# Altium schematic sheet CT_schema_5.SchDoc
size 405 x 220 mm
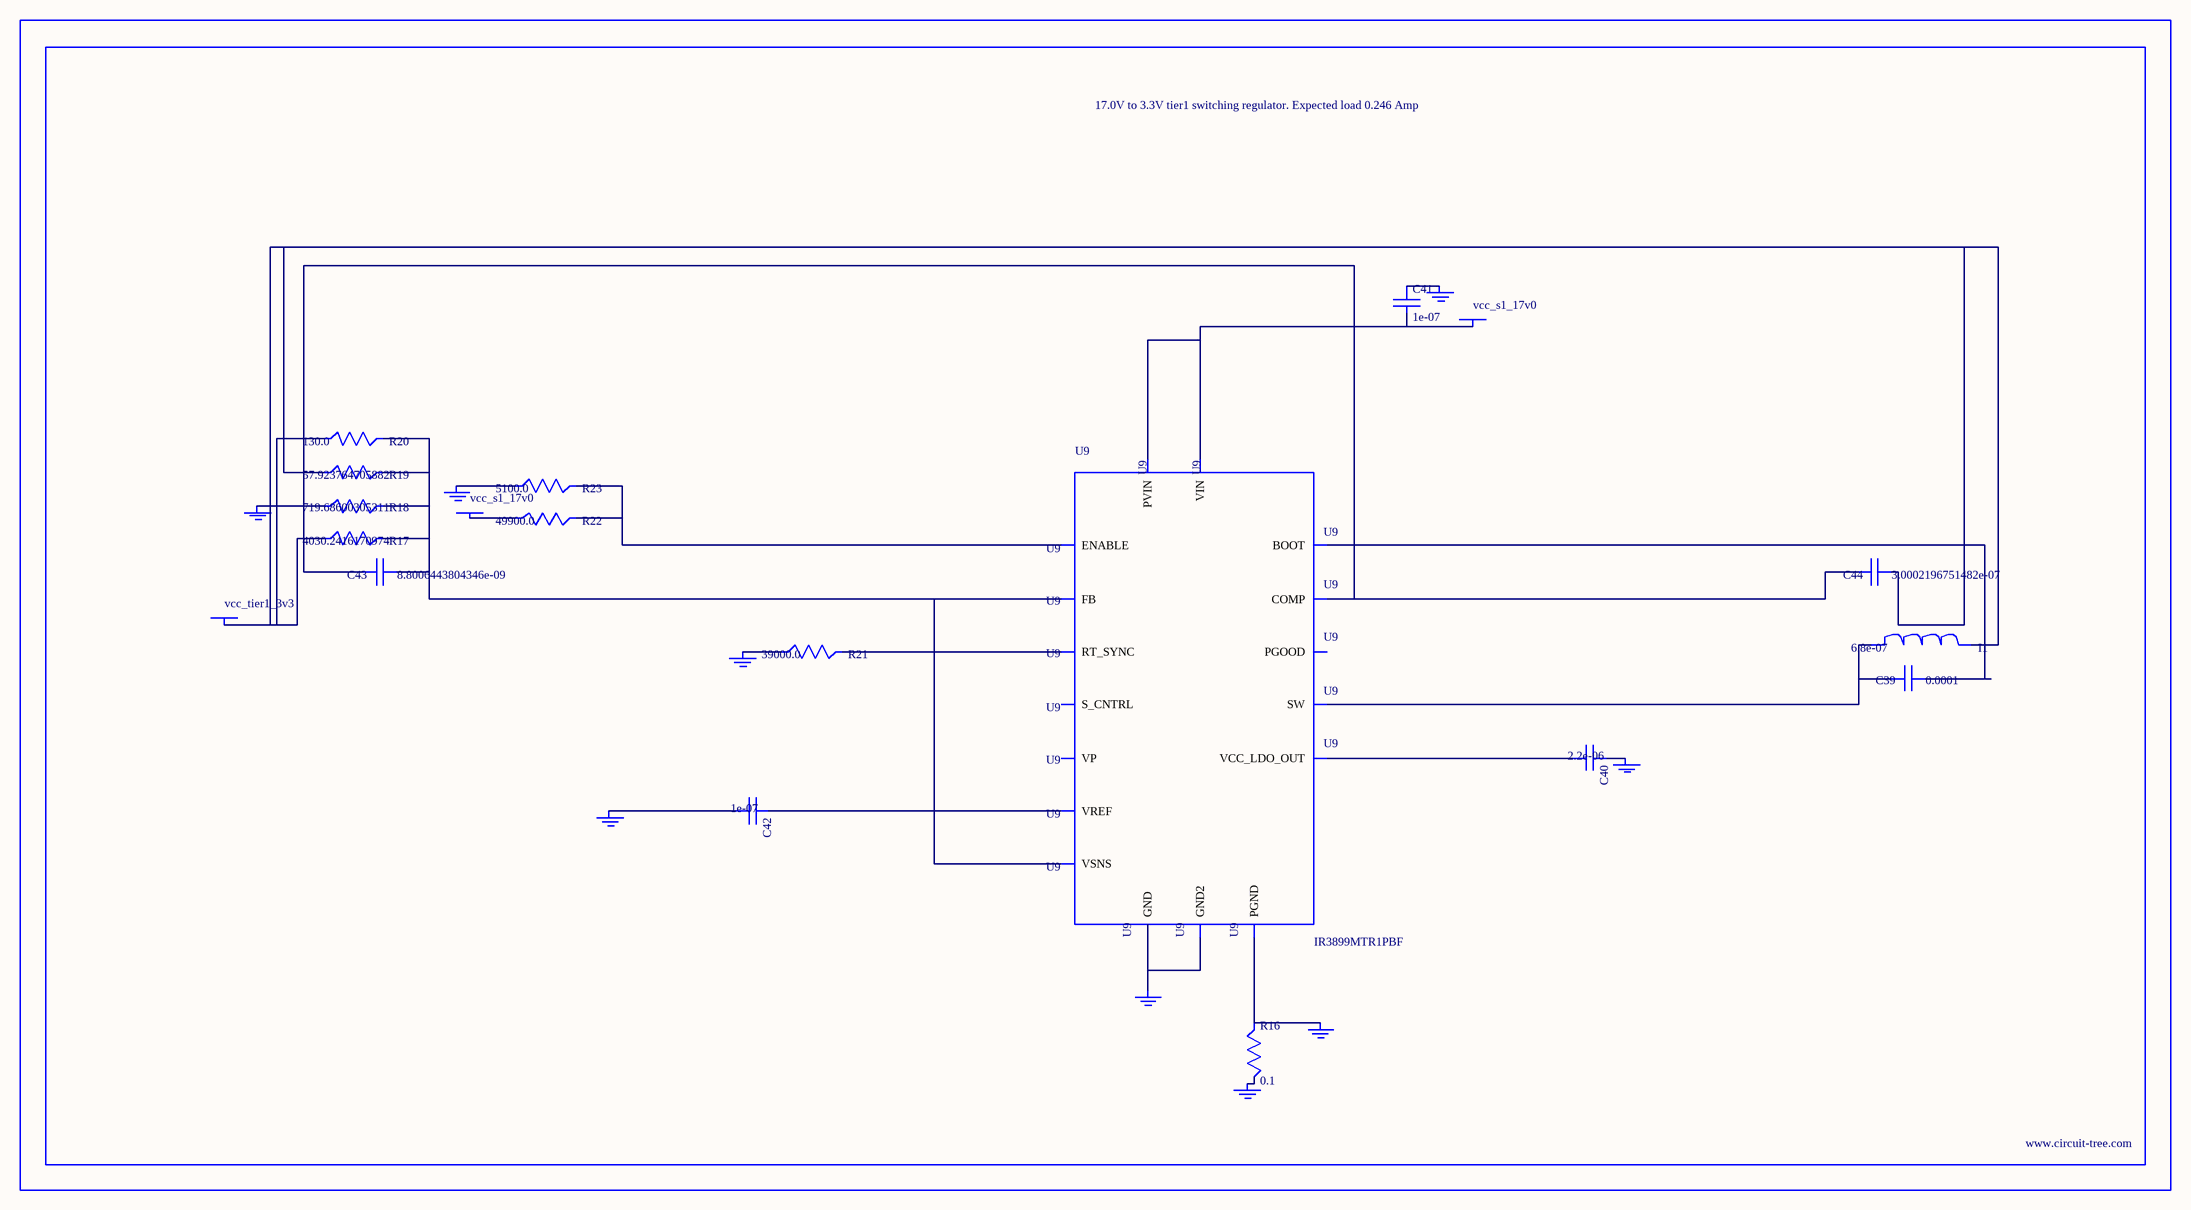
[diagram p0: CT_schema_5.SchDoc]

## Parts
BORDER4  (no value)
C39  0.0001  [C1210]
C40  2.2e-06  [C0603]
C41  1e-07  [C0402]
C42  1e-07  [C0402]
C43  8.8006443804346e-09  [R0603]
C44  3.0002196751482e-07  [R0603]
GND_INSTANCE_4_0  (no value)
GND_INSTANCE_4_1  (no value)
GND_INSTANCE_4_2  (no value)
GND_INSTANCE_4_3  (no value)
GND_INSTANCE_4_4  (no value)
GND_INSTANCE_4_5  (no value)
GND_INSTANCE_4_6  (no value)
GND_INSTANCE_4_7  (no value)
GND_INSTANCE_4_8  (no value)
I1  6.8e-07  [IND25X25CZ]
POWER_INSTANCE_4_0  vcc_s1_17v0
POWER_INSTANCE_4_1  vcc_s1_17v0
POWER_INSTANCE_4_2  vcc_tier1_3v3
R16  0.1  [R0603]
R17  4030.2416170974  [R0603]
R18  719.68600305311  [R0603]
R19  57.923764705882  [R0603]
R20  130.0  [R0603]
R21  39000.0  [R0603]
R22  49900.0  [R0603]
R23  5100.0  [R0603]
U9  IR3899MTR1PBF  [IR3899MTR1PBF]

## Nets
NetC39_1: C39.1 U9.14(BOOT)
NetC39_2: C39.2 I1.1 U9.12(SW)
NetC40_1: C40.1 GND_INSTANCE_4_4.0(GND)
NetC40_2: C40.2 U9.10(VCC_LDO_OUT)
NetC41_1: C41.1 GND_INSTANCE_4_3.0(GND)
NetC41_2: C41.2 POWER_INSTANCE_4_0.0(PWR) U9.9(VIN) U9.13(PVIN)
NetC42_1: C42.1 U9.2(VREF)
NetC42_2: C42.2 GND_INSTANCE_4_1.0(GND)
NetC43_1: C43.1 R17.2 R18.2 R19.2 R20.2 U9.1(FB) U9.8(VSNS)
NetC43_2: C43.2 C44.2 U9.3(COMP)
NetC44_1: C44.1 I1.2 POWER_INSTANCE_4_2.0(PWR) R17.1 R19.1 R20.1
NetGND_INSTANCE_4_0_0: GND_INSTANCE_4_0.0(GND) R18.1
NetGND_INSTANCE_4_2_0: GND_INSTANCE_4_2.0(GND) R21.1
NetGND_INSTANCE_4_5_0: GND_INSTANCE_4_5.0(GND) R16.2
NetGND_INSTANCE_4_6_0: GND_INSTANCE_4_6.0(GND) R16.1 U9.11(PGND)
NetGND_INSTANCE_4_7_0: GND_INSTANCE_4_7.0(GND) R23.1
NetGND_INSTANCE_4_8_0: GND_INSTANCE_4_8.0(GND) U9.4(GND) U9.17(GND2)
NetPOWER_INSTANCE_4_1_0: POWER_INSTANCE_4_1.0(PWR) R22.1
NetR21_2: R21.2 U9.5(RT_SYNC)
NetR22_2: R22.2 R23.2 U9.15(ENABLE)

Not connected (* = marked no-connect by the designer): U9 6(S_CNTRL) 7(PGOOD) 16(VP)

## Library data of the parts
BORDER4 = BORDER_PAGE4
C39 = GRM32ER61A107ME20L
C40 = C0603C225K8RACTU
C41 C42 = C0402C104K3RACTU
C43 = C43
C44 = C44
GND_INSTANCE_4_0-GND_INSTANCE_4_8 = GND
I1 = IHLP2525CZERR68M01
POWER_INSTANCE_4_0-POWER_INSTANCE_4_2 = PWR
R16 = ERJ-3RSFR10V
R17 = R17
R18 = R18
R19 = R19
R20 = RC0603JR-07130RL
R21 = RC0603JR-0739KL
R22 = RC0603FR-0749K9
R23 = RC0603JR-075K1L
